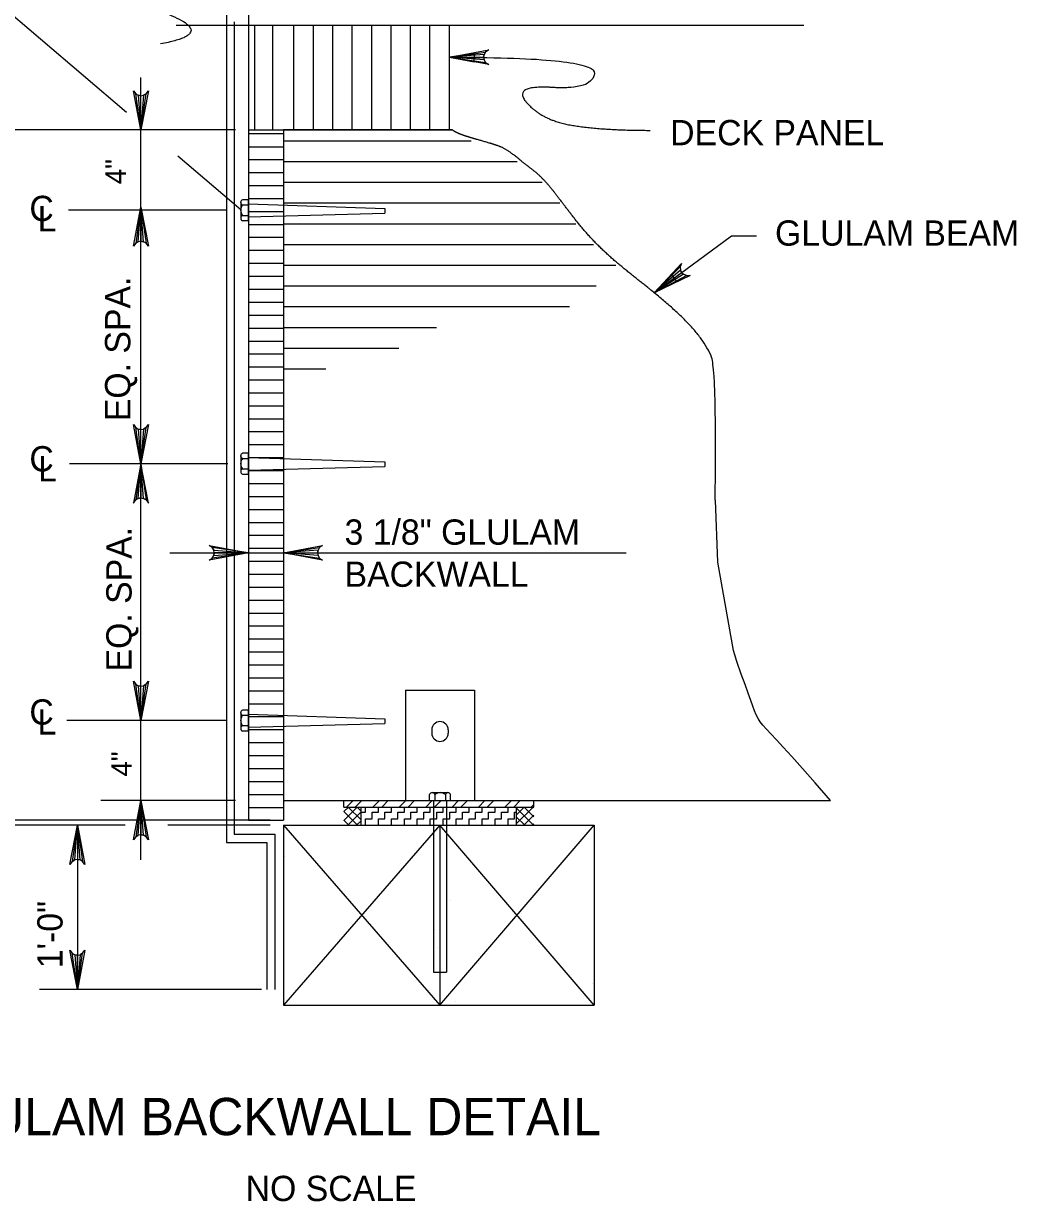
# Model space of a CAD drawing. Extents: x 638263 to 640391, y 293683 to 298655.
# Drawn here: x 639617.3 to 639735.2, y 297622.6 to 297762.5 of the extents above; entities that cross this region are included whole.
import ezdxf

# ---------------------------------------------------------------- set-up
doc = ezdxf.new("R2010")
doc.units = 0
for name, color, linetype in [('3', 7, 'Continuous'), ('5', 7, 'Continuous'), ('7', 7, 'Continuous'), ('8', 7, 'Continuous')]:
    doc.layers.add(name, color=color, linetype=linetype)

msp = doc.modelspace()

# ---------------------------------------------------------------- linework, layer by layer
at = {"layer": '3'}
for p, q in [((639629.53, 297751.9), (639614.19, 297764.97)), ((639631.25, 297740.32), (639631.25, 297756.05)), ((639642.49, 297749.84), (639595.65, 297749.84)), ((639643.09, 297740.36), (639635.63, 297746.71)), ((639641.34, 297740.32), (639622.64, 297740.32)), ((639631.25, 297713.17), (639631.25, 297740.69)), ((639692.16, 297730.52), (639701.36, 297737.27)), ((639701.36, 297737.27), (639704.32, 297737.27)), ((639641.55, 297710.21), (639622.77, 297710.21)), ((639631.25, 297679.74), (639631.25, 297710.21)), ((639634.7, 297699.63), (639688.84, 297699.63)), ((639641.47, 297679.74), (639622.45, 297679.74)), ((639631.25, 297663.18), (639631.25, 297679.74)), ((639642.49, 297670.23), (639626.49, 297670.23)), ((639629.79, 297667.88), (639595.65, 297667.88)), ((639642.49, 297667.88), (639633.92, 297667.88)), ((639623.01, 297667.3), (639619.21, 297667.3)), ((639623.71, 297667.3), (639623.71, 297647.79)), ((639645.56, 297647.79), (639619.21, 297647.79))]:
    msp.add_line(p, q, dxfattribs=at)
for points in [[(639667.87, 297758.47), (639672.53, 297759.34), (639672.17, 297759.09), (639671.98, 297758.78), (639671.93, 297758.47), (639671.98, 297758.16), (639672.17, 297757.84), (639672.53, 297757.6), (639667.87, 297758.47), (639672.17, 297757.84), (639671.98, 297758.16), (639667.87, 297758.47), (639671.93, 297758.47), (639671.98, 297758.78), (639667.87, 297758.47), (639672.17, 297759.09)], [(639631.25, 297749.84), (639630.38, 297754.5), (639630.63, 297754.14), (639630.94, 297753.95), (639631.25, 297753.9), (639631.57, 297753.95), (639631.88, 297754.14), (639632.13, 297754.5), (639631.25, 297749.84), (639631.88, 297754.14), (639631.57, 297753.95), (639631.25, 297749.84), (639631.25, 297753.9), (639630.94, 297753.95), (639631.25, 297749.84), (639630.63, 297754.14)], [(639631.25, 297740.69), (639632.13, 297736.03), (639631.88, 297736.38), (639631.57, 297736.57), (639631.25, 297736.62), (639630.94, 297736.57), (639630.63, 297736.38), (639630.38, 297736.03), (639631.25, 297740.69), (639630.63, 297736.38), (639630.94, 297736.57), (639631.25, 297740.69), (639631.25, 297736.62), (639631.57, 297736.57), (639631.25, 297740.69), (639631.88, 297736.38)], [(639692.16, 297730.52), (639695.4, 297733.98), (639695.26, 297733.57), (639695.29, 297733.21), (639695.43, 297732.92), (639695.66, 297732.7), (639696, 297732.56), (639696.43, 297732.57), (639692.16, 297730.52), (639696, 297732.56), (639695.66, 297732.7), (639692.16, 297730.52), (639695.43, 297732.92), (639695.29, 297733.21), (639692.16, 297730.52), (639695.26, 297733.57)], [(639631.25, 297710.21), (639630.38, 297714.87), (639630.63, 297714.52), (639630.94, 297714.33), (639631.25, 297714.28), (639631.57, 297714.33), (639631.88, 297714.52), (639632.13, 297714.87), (639631.25, 297710.21), (639631.88, 297714.52), (639631.57, 297714.33), (639631.25, 297710.21), (639631.25, 297714.28), (639630.94, 297714.33), (639631.25, 297710.21), (639630.63, 297714.52)], [(639631.25, 297710.21), (639630.38, 297705.55), (639630.63, 297705.91), (639630.94, 297706.1), (639631.25, 297706.15), (639631.57, 297706.1), (639631.88, 297705.91), (639632.13, 297705.55), (639631.25, 297710.21), (639631.88, 297705.91), (639631.57, 297706.1), (639631.25, 297710.21), (639631.25, 297706.15), (639630.94, 297706.1), (639631.25, 297710.21), (639630.63, 297705.91)], [(639644.03, 297699.63), (639639.36, 297698.76), (639639.72, 297699.01), (639639.91, 297699.32), (639639.96, 297699.63), (639639.91, 297699.95), (639639.72, 297700.26), (639639.36, 297700.51), (639644.03, 297699.63), (639639.72, 297700.26), (639639.91, 297699.95), (639644.03, 297699.63), (639639.96, 297699.63), (639639.91, 297699.32), (639644.03, 297699.63), (639639.72, 297699.01)], [(639648.16, 297699.63), (639652.82, 297700.51), (639652.46, 297700.26), (639652.28, 297699.95), (639652.22, 297699.63), (639652.28, 297699.32), (639652.46, 297699.01), (639652.82, 297698.76), (639648.16, 297699.63), (639652.46, 297699.01), (639652.28, 297699.32), (639648.16, 297699.63), (639652.22, 297699.63), (639652.28, 297699.95), (639648.16, 297699.63), (639652.46, 297700.26)], [(639631.25, 297679.74), (639630.38, 297684.4), (639630.63, 297684.04), (639630.94, 297683.86), (639631.25, 297683.8), (639631.57, 297683.86), (639631.88, 297684.04), (639632.13, 297684.4), (639631.25, 297679.74), (639631.88, 297684.04), (639631.57, 297683.86), (639631.25, 297679.74), (639631.25, 297683.8), (639630.94, 297683.86), (639631.25, 297679.74), (639630.63, 297684.04)], [(639631.25, 297670.23), (639632.13, 297665.57), (639631.88, 297665.92), (639631.57, 297666.11), (639631.25, 297666.16), (639630.94, 297666.11), (639630.63, 297665.92), (639630.38, 297665.57), (639631.25, 297670.23), (639630.63, 297665.92), (639630.94, 297666.11), (639631.25, 297670.23), (639631.25, 297666.16), (639631.57, 297666.11), (639631.25, 297670.23), (639631.88, 297665.92)], [(639623.71, 297667.3), (639624.58, 297662.63), (639624.33, 297662.99), (639624.02, 297663.18), (639623.71, 297663.23), (639623.39, 297663.18), (639623.08, 297662.99), (639622.83, 297662.63), (639623.71, 297667.3), (639623.08, 297662.99), (639623.39, 297663.18), (639623.71, 297667.3), (639623.71, 297663.23), (639624.02, 297663.18), (639623.71, 297667.3), (639624.33, 297662.99)], [(639623.71, 297647.79), (639622.83, 297652.45), (639623.08, 297652.1), (639623.39, 297651.91), (639623.71, 297651.86), (639624.02, 297651.91), (639624.33, 297652.1), (639624.58, 297652.45), (639623.71, 297647.79), (639624.33, 297652.1), (639624.02, 297651.91), (639623.71, 297647.79), (639623.71, 297651.86), (639623.39, 297651.91), (639623.71, 297647.79), (639623.08, 297652.1)]]:
    msp.add_lwpolyline(points, dxfattribs=at)
for points in [[(639670.81, 297757.93), (639670.83, 297758.92), (639667.87, 297758.47)], [(639694.84, 297731.87), (639694.25, 297732.67), (639692.16, 297730.52)]]:
    msp.add_lwpolyline(points, close=True, dxfattribs=at)
msp.add_open_spline([(639667.87, 297758.47), (639685.4, 297758.47), (639684.8, 297754.58), (639675.24, 297755.18), (639678.83, 297750.99), (639686, 297749.79), (639691.68, 297749.79)], degree=2, dxfattribs=at)
at = {"layer": '5'}
for p, q in [((639644.03, 297765.87), (639644.03, 297667.88)), ((639641.41, 297763.65), (639641.41, 297665.26)), ((639642.33, 297762.69), (639642.33, 297666.25)), ((639644.79, 297762.25), (639635.43, 297762.25)), ((639709.93, 297762.25), (639644.03, 297762.25)), ((639644.03, 297749.84), (639668.2, 297749.84)), ((639648.16, 297749.84), (639648.16, 297667.88)), ((639643.09, 297741.26), (639643.09, 297739.36)), ((639644.03, 297741.07), (639660.21, 297740.52)), ((639660.21, 297740.52), (639660.21, 297739.97)), ((639644.03, 297739.53), (639660.21, 297739.97)), ((639643.09, 297711.16), (639643.09, 297709.27)), ((639644.03, 297710.97), (639660.21, 297710.42)), ((639644.03, 297709.43), (639660.21, 297709.87)), ((639660.21, 297710.42), (639660.21, 297709.87)), ((639662.67, 297683.35), (639670.83, 297683.35)), ((639662.67, 297683.35), (639662.67, 297670.23)), ((639670.83, 297683.35), (639670.83, 297670.23)), ((639643.09, 297680.68), (639643.09, 297678.78)), ((639644.03, 297680.49), (639660.21, 297679.94)), ((639644.03, 297678.95), (639660.21, 297679.39)), ((639660.21, 297679.94), (639660.21, 297679.39)), ((639665.77, 297678.62), (639665.77, 297678.23)), ((639667.73, 297678.62), (639667.73, 297678.23)), ((639665.5, 297670.23), (639665.5, 297670.94)), ((639667.71, 297671.16), (639665.81, 297671.16)), ((639666.15, 297670.94), (639666.15, 297670.23)), ((639667.39, 297670.94), (639667.39, 297670.23)), ((639668, 297670.23), (639668, 297670.94)), ((639648.16, 297670.23), (639713.09, 297670.23)), ((639655.34, 297670.23), (639677.89, 297670.23)), ((639655.34, 297669.46), (639655.34, 297670.23)), ((639655.34, 297669.46), (639677.89, 297669.46)), ((639655.34, 297667.87), (639656.93, 297669.46)), ((639655.34, 297668.91), (639655.88, 297669.46)), ((639656.97, 297667.3), (639655.34, 297668.93)), ((639655.66, 297669.46), (639656.43, 297670.23)), ((639657.39, 297667.92), (639655.86, 297669.46)), ((639656.7, 297669.46), (639657.48, 297670.23)), ((639657.39, 297668.97), (639656.9, 297669.46)), ((639657.39, 297667.3), (639657.39, 297669.46)), ((639657.91, 297668.83), (639657.91, 297669.46)), ((639658.79, 297669.46), (639659.56, 297670.23)), ((639659.45, 297668.83), (639659.45, 297669.46)), ((639659.84, 297669.46), (639660.61, 297670.23)), ((639660.99, 297668.83), (639660.99, 297669.46)), ((639661.92, 297669.46), (639662.69, 297670.23)), ((639662.52, 297668.83), (639662.52, 297669.46)), ((639662.97, 297669.46), (639663.74, 297670.23)), ((639664.06, 297668.83), (639664.06, 297669.46)), ((639665.06, 297669.46), (639665.83, 297670.23)), ((639665.5, 297670.23), (639668, 297670.23)), ((639665.6, 297668.83), (639665.6, 297669.46)), ((639665.98, 297670.23), (639665.98, 297649.85)), ((639666.1, 297669.46), (639666.87, 297670.23)), ((639667.14, 297668.83), (639667.14, 297669.46)), ((639667.52, 297670.23), (639667.52, 297649.85)), ((639668.19, 297669.46), (639668.96, 297670.23)), ((639668.68, 297668.83), (639668.68, 297669.46)), ((639669.23, 297669.46), (639670, 297670.23)), ((639670.21, 297668.83), (639670.21, 297669.46)), ((639671.32, 297669.46), (639672.09, 297670.23)), ((639671.75, 297668.83), (639671.75, 297669.46)), ((639672.36, 297669.46), (639673.13, 297670.23)), ((639673.29, 297668.83), (639673.29, 297669.46)), ((639674.45, 297669.46), (639675.22, 297670.23)), ((639674.83, 297668.83), (639674.83, 297669.46)), ((639675.5, 297669.46), (639676.26, 297670.23)), ((639675.84, 297668.54), (639676.76, 297669.46)), ((639675.84, 297667.49), (639677.8, 297669.46)), ((639675.84, 297667.3), (639675.84, 297669.46)), ((639677.85, 297667.3), (639675.84, 297669.31)), ((639677.89, 297668.3), (639676.74, 297669.46)), ((639677.58, 297669.46), (639677.89, 297669.76)), ((639677.89, 297669.35), (639677.78, 297669.46)), ((639677.89, 297669.46), (639677.89, 297670.23)), ((639655.93, 297667.3), (639655.34, 297667.88)), ((639655.81, 297667.3), (639657.39, 297668.87)), ((639656.85, 297667.3), (639657.39, 297667.83)), ((639657.39, 297668.83), (639657.91, 297668.83)), ((639657.91, 297668.06), (639658.68, 297668.06)), ((639657.91, 297667.3), (639657.91, 297668.06)), ((639658.68, 297668.83), (639659.45, 297668.83)), ((639658.68, 297668.06), (639658.68, 297668.83)), ((639659.45, 297668.06), (639660.22, 297668.06)), ((639659.45, 297667.3), (639659.45, 297668.06)), ((639660.22, 297668.83), (639660.99, 297668.83)), ((639660.22, 297668.06), (639660.22, 297668.83)), ((639660.99, 297668.06), (639661.75, 297668.06)), ((639660.99, 297667.3), (639660.99, 297668.06)), ((639661.75, 297668.83), (639662.52, 297668.83)), ((639661.75, 297668.06), (639661.75, 297668.83)), ((639662.52, 297668.06), (639663.29, 297668.06)), ((639662.52, 297667.3), (639662.52, 297668.06)), ((639663.29, 297668.83), (639664.06, 297668.83)), ((639663.29, 297668.06), (639663.29, 297668.83)), ((639664.06, 297668.06), (639664.83, 297668.06)), ((639664.06, 297667.3), (639664.06, 297668.06)), ((639664.83, 297668.83), (639665.6, 297668.83)), ((639664.83, 297668.06), (639664.83, 297668.83)), ((639665.6, 297668.06), (639666.37, 297668.06)), ((639665.6, 297667.3), (639665.6, 297668.06)), ((639666.37, 297668.83), (639667.14, 297668.83)), ((639666.37, 297668.06), (639666.37, 297668.83)), ((639667.14, 297668.06), (639667.91, 297668.06)), ((639667.14, 297667.3), (639667.14, 297668.06)), ((639667.91, 297668.83), (639668.68, 297668.83)), ((639667.91, 297668.06), (639667.91, 297668.83)), ((639668.68, 297668.06), (639669.44, 297668.06)), ((639668.68, 297667.3), (639668.68, 297668.06)), ((639669.44, 297668.83), (639670.21, 297668.83)), ((639669.44, 297668.06), (639669.44, 297668.83)), ((639670.21, 297668.06), (639670.98, 297668.06)), ((639670.21, 297667.3), (639670.21, 297668.06)), ((639670.98, 297668.83), (639671.75, 297668.83)), ((639670.98, 297668.06), (639670.98, 297668.83)), ((639671.75, 297668.06), (639672.52, 297668.06)), ((639671.75, 297667.3), (639671.75, 297668.06)), ((639672.52, 297668.83), (639673.29, 297668.83)), ((639672.52, 297668.06), (639672.52, 297668.83)), ((639673.29, 297668.06), (639674.06, 297668.06)), ((639673.29, 297667.3), (639673.29, 297668.06)), ((639674.06, 297668.83), (639674.83, 297668.83)), ((639674.06, 297668.06), (639674.06, 297668.83)), ((639674.83, 297668.06), (639675.6, 297668.06)), ((639674.83, 297667.3), (639674.83, 297668.06)), ((639675.6, 297668.83), (639675.84, 297668.83)), ((639675.6, 297668.06), (639675.6, 297668.83)), ((639676.81, 297667.3), (639675.84, 297668.26)), ((639676.69, 297667.3), (639677.89, 297668.5)), ((639642.33, 297666.25), (639647.13, 297666.25)), ((639647.13, 297666.25), (639647.13, 297647.79)), ((639648.16, 297667.3), (639685.07, 297667.3)), ((639648.16, 297667.3), (639648.16, 297645.95)), ((639648.16, 297667.3), (639666.75, 297645.95)), ((639666.75, 297667.3), (639648.16, 297645.95)), ((639666.75, 297667.3), (639666.75, 297645.95)), ((639666.75, 297645.95), (639685.07, 297667.3)), ((639685.07, 297645.95), (639666.75, 297667.3)), ((639676.18, 297667.29), (639676.18, 297667.29)), ((639677.73, 297667.3), (639677.89, 297667.45)), ((639685.07, 297667.3), (639685.07, 297645.95)), ((639641.41, 297665.26), (639646.2, 297665.26)), ((639646.2, 297665.26), (639646.2, 297647.79)), ((639648.29, 297663.62), (639648.29, 297663.62)), ((639648.26, 297659.21), (639648.26, 297659.21)), ((639666.7, 297659.4), (639666.7, 297659.4)), ((639667.96, 297658.38), (639667.96, 297658.38)), ((639666.08, 297654.93), (639666.08, 297654.93)), ((639666.46, 297652.73), (639666.46, 297652.73)), ((639665.98, 297649.85), (639667.52, 297649.85)), ((639684.87, 297648.52), (639684.87, 297648.52)), ((639648.16, 297645.95), (639685.07, 297645.95)), ((639668.6, 297646.37), (639668.6, 297646.37))]:
    msp.add_line(p, q, dxfattribs=at)
msp.add_lwpolyline([(639668.2, 297749.84), (639667.79, 297749.84), (639648.16, 297749.84), (639648.16, 297685.74)], dxfattribs=at)
for centre, radius, start, end in [((639643.4, 297741.25), 0.316, 107.4518, 252.5482), ((639644.08, 297740.32), 0.994, 141.05, 218.95), ((639643.44, 297739.37), 0.347, 111.2869, 178.1729), ((639643.44, 297739.37), 0.347, 178.1729, 248.7131), ((639643.4, 297711.15), 0.316, 107.4518, 252.5482), ((639644.08, 297710.22), 0.994, 141.05, 218.95), ((639643.44, 297709.28), 0.347, 111.2869, 178.1729), ((639643.44, 297709.28), 0.347, 178.1729, 248.7131), ((639643.4, 297680.67), 0.316, 107.4518, 252.5482), ((639644.08, 297679.74), 0.994, 141.05, 218.95), ((639643.44, 297678.79), 0.347, 111.2869, 178.1729), ((639643.44, 297678.79), 0.347, 178.1729, 248.7131), ((639666.75, 297678.62), 0.976, 0, 180), ((639666.75, 297678.23), 0.976, 180, 0), ((639665.82, 297670.82), 0.347, 88.1729, 158.7131), ((639665.82, 297670.82), 0.347, 21.2869, 88.1729), ((639666.77, 297670.17), 0.994, 51.05, 128.95), ((639667.69, 297670.85), 0.316, 17.4518, 162.5482)]:
    msp.add_arc(centre, radius, start, end, dxfattribs=at)
msp.add_open_spline([(639632.93, 297767.68), (639629.56, 297765.66), (639640.11, 297761.2), (639633.58, 297760.06)], degree=2, dxfattribs=at)
at = {"layer": '7'}
for p, q in [((639644.79, 297749.84), (639644.79, 297762.25)), ((639646.9, 297749.84), (639646.9, 297762.25)), ((639649.41, 297749.84), (639649.41, 297762.25)), ((639651.72, 297749.84), (639651.72, 297762.25)), ((639654.03, 297749.84), (639654.03, 297762.25)), ((639656.33, 297749.84), (639656.33, 297762.25)), ((639658.64, 297749.84), (639658.64, 297762.25)), ((639660.95, 297749.84), (639660.95, 297762.25)), ((639663.25, 297749.84), (639663.25, 297762.25)), ((639665.56, 297749.84), (639665.56, 297762.25)), ((639667.87, 297749.84), (639667.87, 297762.25)), ((639644.03, 297749.84), (639644.03, 297749.84)), ((639644.03, 297749.41), (639648.16, 297749.41)), ((639648.16, 297749.84), (639648.16, 297749.84)), ((639644.03, 297747.85), (639648.16, 297747.85)), ((639648.16, 297748.55), (639670.45, 297748.55)), ((639644.03, 297746.32), (639648.16, 297746.32)), ((639648.17, 297746.09), (639675.91, 297746.09)), ((639644.03, 297744.78), (639648.16, 297744.78)), ((639644.03, 297743.24), (639648.16, 297743.24)), ((639648.17, 297743.63), (639678.86, 297743.63)), ((639644.03, 297741.7), (639648.16, 297741.7)), ((639644.03, 297741.55), (639643.31, 297741.55)), ((639643.31, 297740.95), (639644.03, 297740.95)), ((639644.03, 297739.05), (639644.03, 297741.55)), ((639648.18, 297741.17), (639680.96, 297741.17)), ((639643.31, 297739.7), (639644.03, 297739.7)), ((639644.03, 297739.05), (639643.31, 297739.05)), ((639644.03, 297740.16), (639648.16, 297740.16)), ((639644.03, 297738.63), (639648.16, 297738.63)), ((639648.18, 297738.71), (639682.88, 297738.71)), ((639644.03, 297737.09), (639648.16, 297737.09)), ((639648.19, 297736.24), (639684.99, 297736.24)), ((639644.03, 297735.55), (639648.16, 297735.55)), ((639644.03, 297734.01), (639648.16, 297734.01)), ((639648.19, 297733.78), (639687.61, 297733.78)), ((639644.03, 297732.47), (639648.16, 297732.47)), ((639644.03, 297730.94), (639648.16, 297730.94)), ((639648.2, 297731.32), (639685.27, 297731.32)), ((639644.03, 297729.4), (639648.16, 297729.4)), ((639644.03, 297727.86), (639648.16, 297727.86)), ((639648.2, 297728.86), (639682.12, 297728.86)), ((639644.03, 297726.32), (639648.16, 297726.32)), ((639648.2, 297726.4), (639666.34, 297726.4)), ((639644.03, 297724.78), (639648.16, 297724.78)), ((639648.21, 297723.94), (639661.85, 297723.94)), ((639644.03, 297723.25), (639648.16, 297723.25)), ((639644.03, 297721.71), (639648.16, 297721.71)), ((639648.21, 297721.48), (639653.21, 297721.48)), ((639644.03, 297720.17), (639648.16, 297720.17)), ((639644.03, 297718.63), (639648.16, 297718.63)), ((639644.03, 297717.1), (639648.16, 297717.1)), ((639644.03, 297715.56), (639648.16, 297715.56)), ((639644.03, 297714.02), (639648.16, 297714.02)), ((639644.03, 297712.48), (639648.16, 297712.48)), ((639644.03, 297711.45), (639643.31, 297711.45)), ((639643.31, 297710.85), (639644.03, 297710.85)), ((639644.03, 297708.95), (639644.03, 297711.45)), ((639644.03, 297710.94), (639648.16, 297710.94)), ((639643.31, 297709.6), (639644.03, 297709.6)), ((639644.03, 297708.95), (639643.31, 297708.95)), ((639644.03, 297709.41), (639648.16, 297709.41)), ((639644.03, 297707.87), (639648.16, 297707.87)), ((639644.03, 297706.33), (639648.16, 297706.33)), ((639644.03, 297704.79), (639648.16, 297704.79)), ((639644.03, 297703.25), (639648.16, 297703.25)), ((639644.03, 297701.72), (639648.16, 297701.72)), ((639644.03, 297700.18), (639648.16, 297700.18)), ((639644.03, 297698.64), (639648.16, 297698.64)), ((639644.03, 297697.1), (639648.16, 297697.1)), ((639644.03, 297695.56), (639648.16, 297695.56)), ((639644.03, 297694.03), (639648.16, 297694.03)), ((639644.03, 297692.49), (639648.16, 297692.49)), ((639644.03, 297690.95), (639648.16, 297690.95)), ((639644.03, 297689.41), (639648.16, 297689.41)), ((639644.03, 297687.87), (639648.16, 297687.87)), ((639644.03, 297686.34), (639648.16, 297686.34)), ((639644.03, 297684.8), (639648.16, 297684.8)), ((639644.03, 297683.26), (639648.16, 297683.26)), ((639644.03, 297681.72), (639648.16, 297681.72)), ((639644.03, 297680.97), (639643.31, 297680.97)), ((639643.31, 297680.37), (639644.03, 297680.37)), ((639644.03, 297678.47), (639644.03, 297680.97)), ((639644.03, 297680.19), (639648.16, 297680.19)), ((639643.31, 297679.12), (639644.03, 297679.12)), ((639644.03, 297678.47), (639643.31, 297678.47)), ((639644.03, 297678.65), (639648.16, 297678.65)), ((639644.03, 297677.11), (639648.16, 297677.11)), ((639644.03, 297675.57), (639648.16, 297675.57)), ((639644.03, 297674.03), (639648.16, 297674.03)), ((639644.03, 297672.5), (639648.16, 297672.5)), ((639644.03, 297670.96), (639648.16, 297670.96)), ((639644.03, 297669.42), (639648.16, 297669.42)), ((639644.03, 297667.88), (639648.16, 297667.88))]:
    msp.add_line(p, q, dxfattribs=at)
for points in [[(639701.59, 297688.04), (639699.74, 297698.53), (639699.45, 297705.87)], [(639713.09, 297670.23), (639711.3, 297672.32), (639709.79, 297674.04), (639708.53, 297675.44), (639707.5, 297676.55), (639706.68, 297677.44), (639706.01, 297678.13), (639705.5, 297678.69), (639705.09, 297679.16), (639704.77, 297679.57), (639704.51, 297679.97), (639704.29, 297680.39), (639704.08, 297680.87), (639703.87, 297681.43), (639703.63, 297682.12), (639703.33, 297682.96), (639702.96, 297683.99), (639702.51, 297685.25), (639701.99, 297686.75), (639701.59, 297688.04)]]:
    msp.add_lwpolyline(points, dxfattribs=at)
msp.add_open_spline([(639699.4, 297705.87), (639699.5, 297710.63), (639699.35, 297722.07), (639698.52, 297723.95), (639697.26, 297725.75), (639695.66, 297727.47), (639693.84, 297729.13), (639691.89, 297730.75), (639689.9, 297732.33), (639687.98, 297733.88), (639686.22, 297735.43), (639684.7, 297736.96), (639683.39, 297738.47), (639682.23, 297739.94), (639681.19, 297741.32), (639680.2, 297742.61), (639679.22, 297743.77), (639678.2, 297744.77), (639677.07, 297745.61), (639674.59, 297747.6), (639673.26, 297748.09), (639671.91, 297748.49), (639670.62, 297748.85), (639669.45, 297749.21), (639668.47, 297749.63), (639668.15, 297749.88)], degree=2, dxfattribs=at)
at = {"layer": '8'}
for p, q in [((639646.6, 297667.88), (639595.58, 297667.88)), ((639629.39, 297667.3), (639595.58, 297667.3)), ((639646.6, 297667.3), (639634.45, 297667.3))]:
    msp.add_line(p, q, dxfattribs=at)

# ---------------------------------------------------------------- texts
at = {"layer": '3'}
for s, height, p in [('DECK PANEL', 3, (639694.07, 297748.02)), ('C', 3, (639618.01, 297739.02)), ('L', 3, (639618.99, 297737.79)), ('GLULAM BEAM', 3, (639706.52, 297736.1)), ('C', 3, (639618.01, 297709.3)), ('L', 3, (639619.05, 297708.12)), ('3 1/8" GLULAM', 3, (639655.42, 297700.6)), ('BACKWALL', 3, (639655.42, 297695.6)), ('C', 3, (639618.01, 297679.24)), ('L', 3, (639618.98, 297678.06)), ('GLULAM BACKWALL DETAIL', 4.4292, (639605.22, 297630.5)), ('NO SCALE', 3, (639643.68, 297622.68))]:
    msp.add_text(s, height=height, dxfattribs=at).set_placement(p)
for s, height, p in [('4"', 2.444, (639629.46, 297743.4)), ('EQ. SPA.', 3, (639629.99, 297715.26)), ('EQ. SPA.', 3, (639630.14, 297685.55)), ('4"', 2.444, (639630.17, 297673.08)), ('1\'-0"', 3, (639621.95, 297650.32))]:
    msp.add_text(s, height=height, rotation=90, dxfattribs=at).set_placement(p)

doc.saveas('drawing.dxf')
